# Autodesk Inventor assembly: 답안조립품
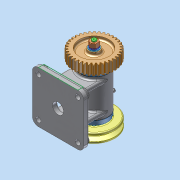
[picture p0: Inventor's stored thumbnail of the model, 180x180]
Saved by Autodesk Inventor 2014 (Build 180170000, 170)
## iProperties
Created: 2025-10
Part Number: 답안조립품
Document SubType Name: Assembly
Designer: dg
Author: dg
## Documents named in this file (17)
- C:\Users\dg\Desktop\751003V1008\답안조립품.iam
- C:\Users\dg\Desktop\751003V1008\본체.ipt
- C:\Users\dg\Desktop\751003V1008\가져온 구성요소\6각 구멍붙이 볼트 M4x10\6각 구멍붙이 볼트 M4x10.ipt
- C:\Users\dg\Desktop\751003V1008\가져온 구성요소\6각 너트 M8x1\6각 너트 M8x1.ipt
- C:\Users\dg\Desktop\751003V1008\가져온 구성요소\6각 머리 볼트 M6x0.75x8\6각 머리 볼트 M6x0.75x8.ipt
- C:\Users\dg\Desktop\751003V1008\가져온 구성요소\V 벨트 풀리\V 벨트 풀리.ipt
- C:\Users\dg\Desktop\751003V1008\가져온 구성요소\가스켓\가스켓.ipt
- C:\Users\dg\Desktop\751003V1008\가져온 구성요소\그리스 니플 M6x0.75\그리스 니플 M6x0.75.ipt
- C:\Users\dg\Desktop\751003V1008\가져온 구성요소\깊은 홈 볼 베어링 6002\깊은 홈 볼 베어링 6002.ipt
- C:\Users\dg\Desktop\751003V1008\가져온 구성요소\스퍼 기어\스퍼 기어.ipt
- C:\Users\dg\Desktop\751003V1008\가져온 구성요소\스프링 와셔 M8\스프링 와셔 M8.ipt
- C:\Users\dg\Desktop\751003V1008\가져온 구성요소\실링\실링.ipt
- C:\Users\dg\Desktop\751003V1008\가져온 구성요소\오일 실 15 25 4\오일 실 15 25 4.ipt
- C:\Users\dg\Desktop\751003V1008\가져온 구성요소\축\축.ipt
- C:\Users\dg\Desktop\751003V1008\가져온 구성요소\커버\커버.ipt
- C:\Users\dg\Desktop\751003V1008\가져온 구성요소\평 와셔 M8\평 와셔 M8.ipt
- C:\Users\dg\Desktop\751003V1008\가져온 구성요소\평행 키 3x3x12\평행 키 3x3x12.ipt
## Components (14 placed, 6 different names)
1. V 벨트 풀리:1
2. 6각 너트 M8x1:1
3. 가스켓:1
4. 6각 머리 볼트 M6x0.75x8:1
5. 그리스 니플 M6x0.75:1
6. 가스켓:2
7. 그리스 니플 M6x0.75:2
8. 6각 너트 M8x1:2
9. 6각 구멍붙이 볼트 M4x10:1 — 각도:1
10. 6각 구멍붙이 볼트 M4x10:3
11. 6각 구멍붙이 볼트 M4x10:4
12. 6각 구멍붙이 볼트 M4x10:2 — 각도:2
13. 6각 구멍붙이 볼트 M4x10:5
14. 6각 구멍붙이 볼트 M4x10:6
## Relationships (2: Angle 2)
- 각도:1 [Angle]: 6각 구멍붙이 볼트 M4x10:1
- 각도:2 [Angle]: 6각 구멍붙이 볼트 M4x10:2
